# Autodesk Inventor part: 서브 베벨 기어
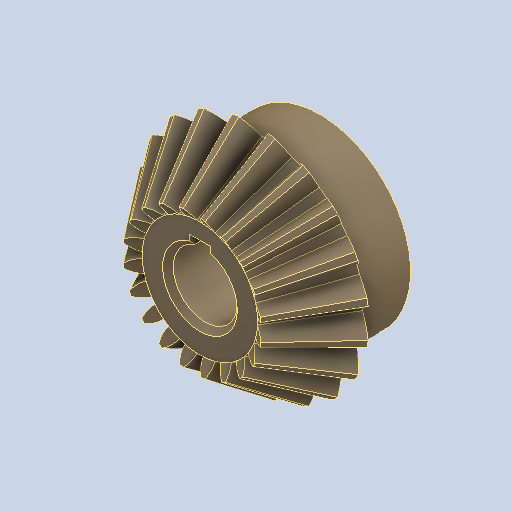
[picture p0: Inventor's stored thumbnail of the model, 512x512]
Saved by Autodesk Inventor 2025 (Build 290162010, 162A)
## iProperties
Created: 2024-07
Part Number: 서브 베벨 기어
Material: 강철, 탄소
Document SubType Name: Modeling
Designer: Admin
Density: 7.87 g/cm^3
Appearance: 기본값
Author: jhkim
Revision Number: 1
Sending System: Autodesk Inventor 2025
Preprocessor: ST-DEVELOPER v20
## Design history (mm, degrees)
node "복구된 형상1"
  node "스케치11"
feature "Solid1"
node "스케치10"
node "솔리드1"
